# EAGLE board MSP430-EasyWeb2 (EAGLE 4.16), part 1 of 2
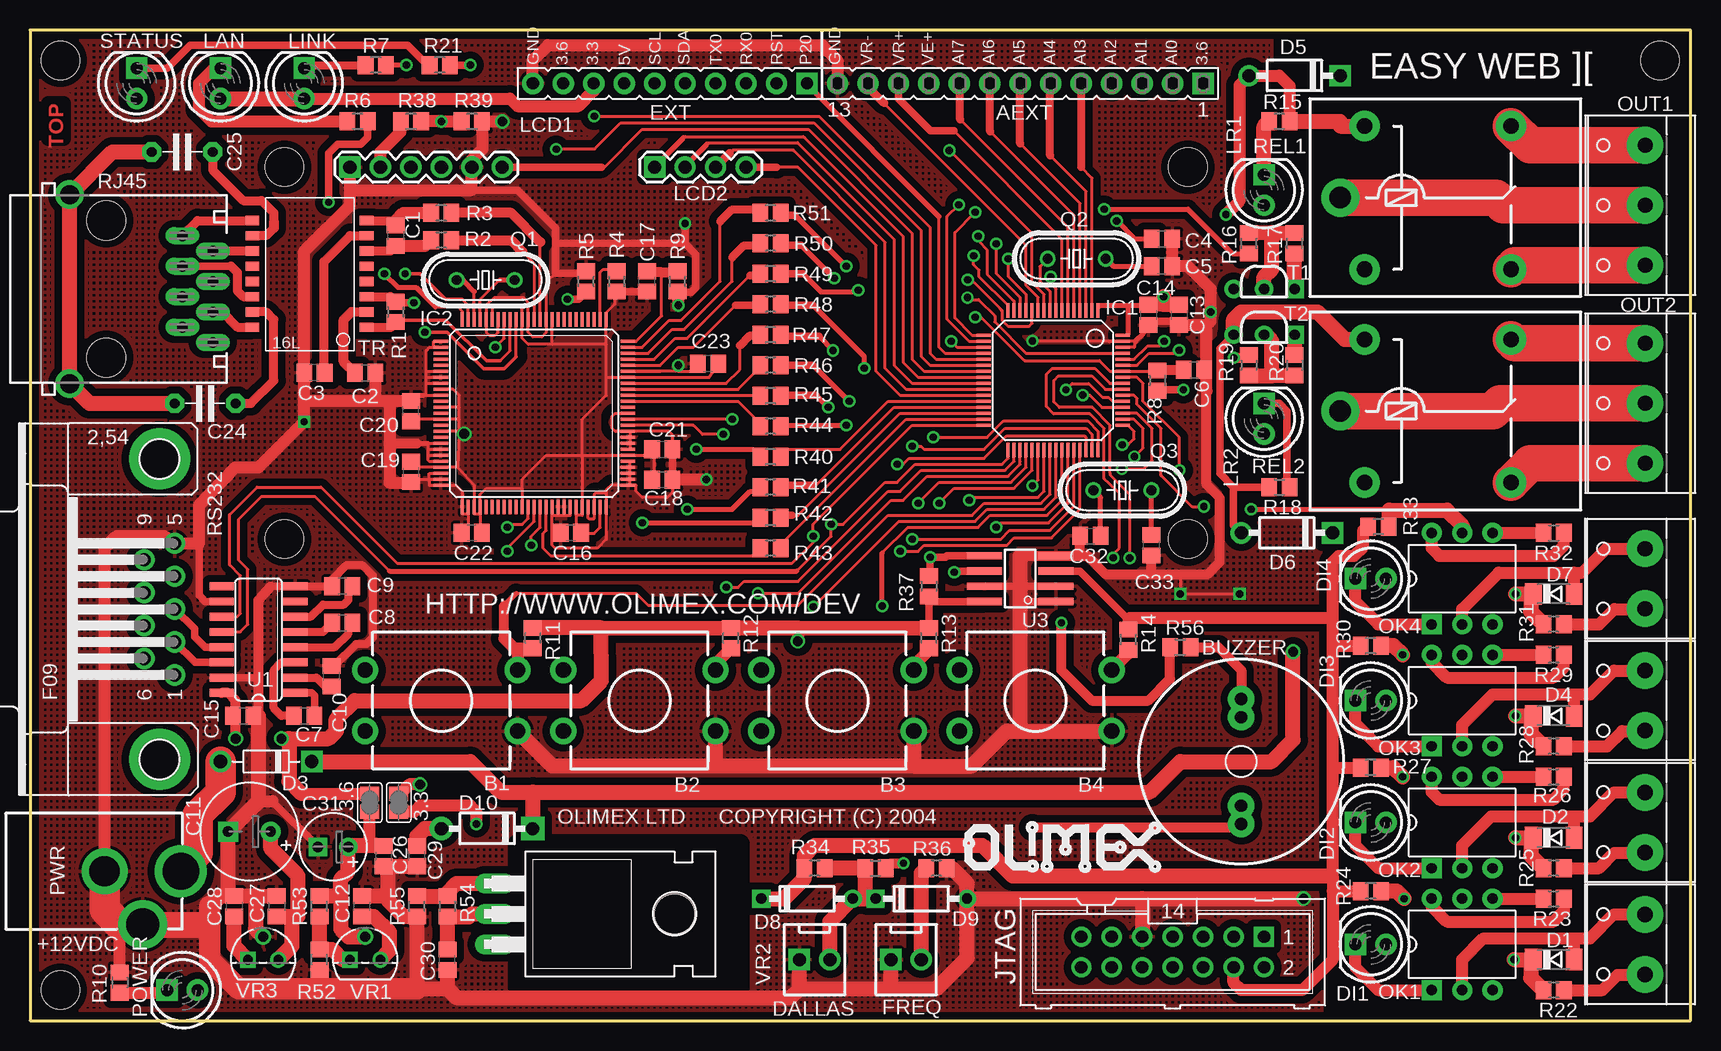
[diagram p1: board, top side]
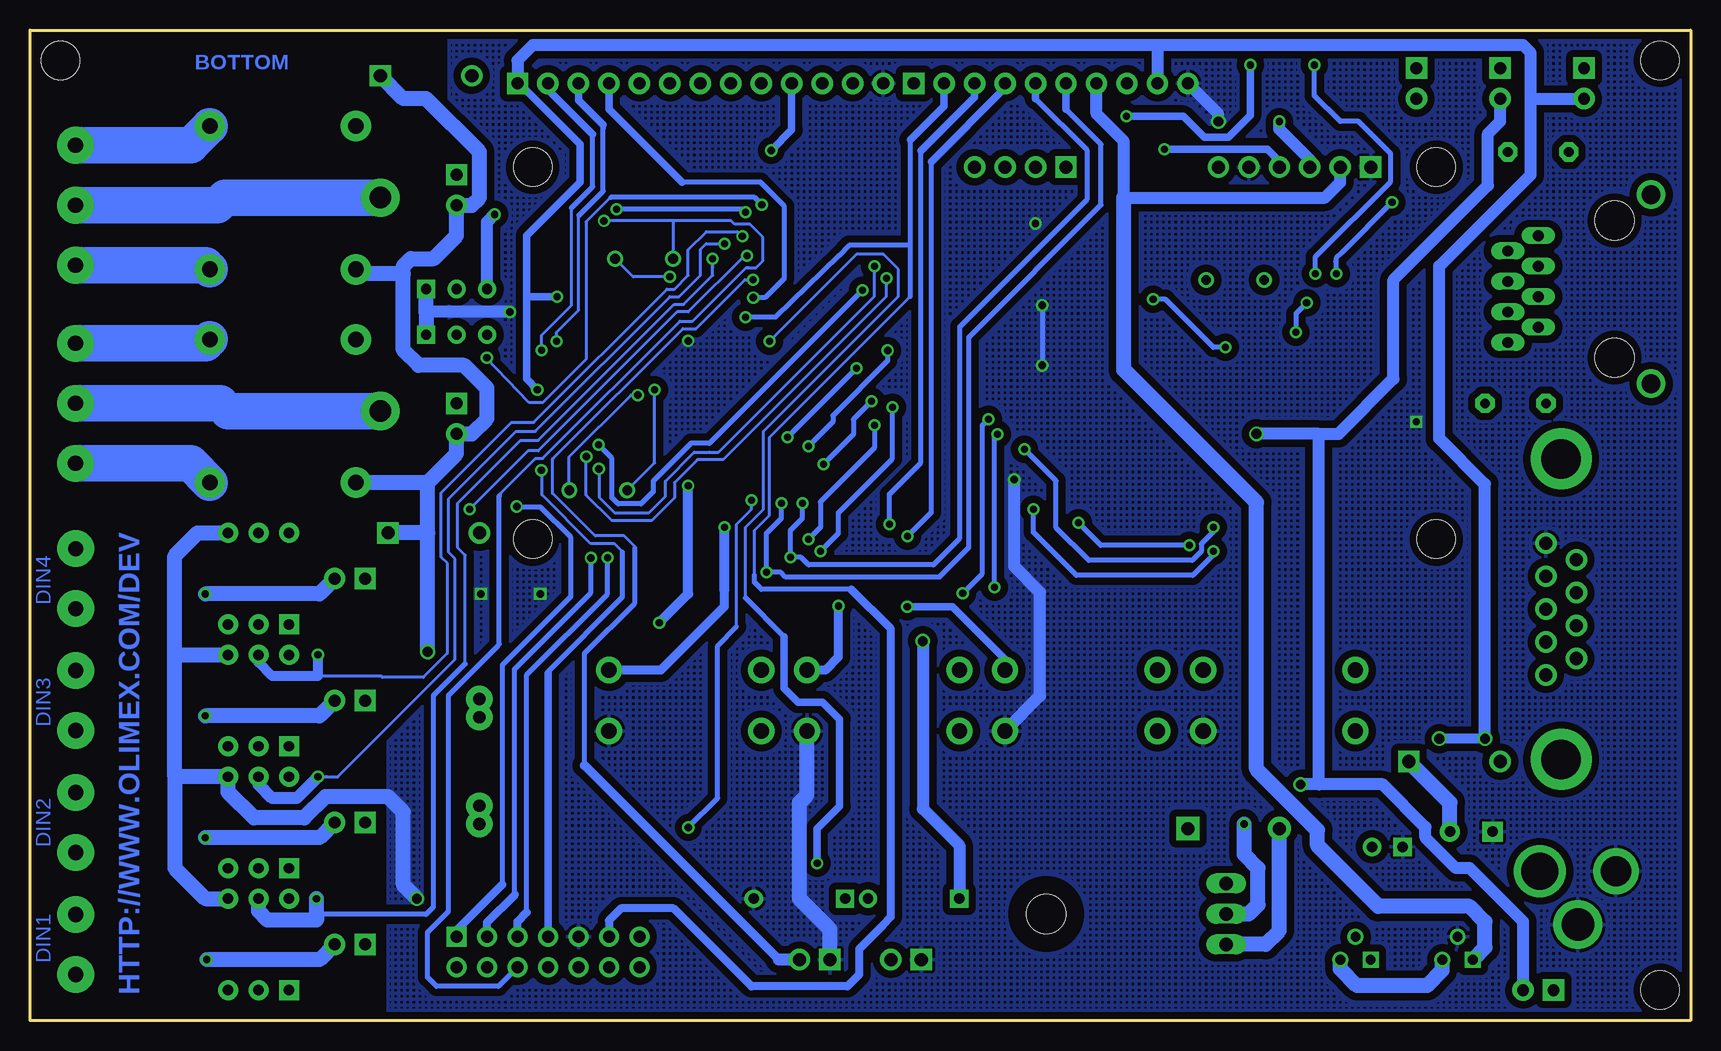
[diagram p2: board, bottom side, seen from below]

Size 138.43 x 82.55 mm. Coordinates in mm from the lower left corner, seen from the top.
Outline: 0,0 138.43,0 138.43,82.55 0,82.55 0,0
Copper layers (1*16): Top 0.035mm / dielectric 1.5mm / Bottom 0.035mm
Design rules "default": minimum track width 0.2489mm, minimum drill 24mil, track to track 9.5mil, track to pad 9.5mil, pad to pad 9.5mil, via to via 10mil, smd to smd 5mil, copper to edge 20mil, drill to drill 10mil, minimum pad ring 10mil, minimum via ring 8mil, stop-mask expansion 4mil, vias tented up to drill 25mil, thermal gap 10mil
Net classes: 0 default: width 0.241 mm, drill 0.241 mm, clearance 0.61 mm; 1 PWR: width 0.241 mm, drill 0.241 mm, clearance 0.61 mm
Holes 3.2 mm at 2.54,2.54 96.52,71.12 2.54,80.01 135.89,80.01 21.21,71.12 21.21,40.13 96.52,40.13
tRestrict: area 40.6,2.8 to 59.2,14.7

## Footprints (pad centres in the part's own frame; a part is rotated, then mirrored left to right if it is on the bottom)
SJ = smd 1.168 x 1.6: 1 -0.762,0; 2 0.762,0
FE13 = drill 1.016 pad 1.778 square: 1 -15.24,0 | drill 1.016 pad 1.778 round: 2 -12.7,0; 3 -10.16,0; 4 -7.62,0; 5 -5.08,0; 6 -2.54,0; 7 0,0; 8 2.54,0; 9 5.08,0; 10 7.62,0; 11 10.16,0; 12 12.7,0; 13 15.24,0
SW_TAKT12X12 = drill 1.27 pad 2.184 round: P$1 -2.54,-6.35; P$2 2.54,-6.35; P$3 2.54,6.35; P$4 -2.54,6.35
BUZ1 = drill 1.016 pad 2.184 round: + 5.207,0; - -5.207,0; P$1 -3.683,0; P$2 3.683,0
C0805 = smd 1.3 x 1.5: 1 -0.85,0; 2 0.85,0
E3,5-8 = drill 0.864 pad 1.676 round: + -1.778,0 | drill 0.864 pad 1.676 square: - 1.778,0
C-5 = drill 0.813 pad 1.6 octagon: 1 -2.54,0; 2 2.54,0
E2,5-6 = drill 0.864 pad 1.524 round: + -1.27,0 | drill 0.864 pad 1.524 square: - 1.27,0
SOD80C = smd 1.4 x 1.8: A 1.7,0; C -1.7,0
D-7.5 = drill 1.092 pad 1.778 round: A 3.81,0 | drill 1.092 pad 1.778 square: C -3.81,0
DO41-10 = drill 1.092 pad 1.778 round: A 3.81,0 | drill 1.092 pad 1.778 square: K -3.81,0
DO35-10 = drill 0.864 pad 1.524 round: A 3.81,0 | drill 0.864 pad 1.524 square: K -3.81,0
1N4742 = drill 1.092 pad 1.93 round: A 3.81,0 | drill 1.092 pad 1.93 square: K -3.81,0
CON2.54MM-2-0 = drill 1.092 pad 1.778 square: 1 -1.27,0 | drill 1.092 pad 1.778 round: 2 1.27,0
LED-5.0MM = drill 0.991 pad 1.778 round: A -1.27,0 | drill 0.991 pad 1.778 square: K 1.27,0
W237-102 = drill 1.27 pad 3.048 round: 1 -2.5,-1.27; 2 2.5,-1.27
FE10 = drill 1.016 pad 1.778 square: 1 -11.43,0 | drill 1.016 pad 1.778 round: 2 -8.89,0; 3 -6.35,0; 4 -3.81,0; 5 -1.27,0; 6 1.27,0; 7 3.81,0; 8 6.35,0; 9 8.89,0; 10 11.43,0
S-PQFP-G = smd 0.25 x 1.2: 1 -3.75,-5.8; 2 -3.25,-5.8; 3 -2.75,-5.8; 4 -2.25,-5.8; 5 -1.75,-5.8; 6 -1.25,-5.8; 7 -0.75,-5.8; 8 -0.25,-5.8; 9 0.25,-5.8; 10 0.75,-5.8; 11 1.25,-5.8; 12 1.75,-5.8; 13 2.25,-5.8; 14 2.75,-5.8; 15 3.25,-5.8; 16 3.75,-5.8; 33 3.75,5.8; 34 3.25,5.8; 35 2.75,5.8; 36 2.25,5.8; 37 1.75,5.8; 38 1.25,5.8; 39 0.75,5.8; 40 0.25,5.8; 41 -0.25,5.8; 42 -0.75,5.8; 43 -1.25,5.8; 44 -1.75,5.8; 45 -2.25,5.8; 46 -2.75,5.8; 47 -3.25,5.8; 48 -3.75,5.8 | smd 1.2 x 0.25: 17 5.8,-3.75; 18 5.8,-3.25; 19 5.8,-2.75; 20 5.8,-2.25; 21 5.8,-1.75; 22 5.8,-1.25; 23 5.8,-0.75; 24 5.8,-0.25; 25 5.8,0.25; 26 5.8,0.75; 27 5.8,1.25; 28 5.8,1.75; 29 5.8,2.25; 30 5.8,2.75; 31 5.8,3.25; 32 5.8,3.75; 49 -5.8,3.75; 50 -5.8,3.25; 51 -5.8,2.75; 52 -5.8,2.25; 53 -5.8,1.75; 54 -5.8,1.25; 55 -5.8,0.75; 56 -5.8,0.25; 57 -5.8,-0.25; 58 -5.8,-0.75; 59 -5.8,-1.25; 60 -5.8,-1.75; 61 -5.8,-2.25; 62 -5.8,-2.75; 63 -5.8,-3.25; 64 -5.8,-3.75
100LTQFP = smd 0.25 x 1.2: 1 -6,-7.8; 2 -5.5,-7.8; 3 -5,-7.8; 4 -4.5,-7.8; 5 -4,-7.8; 6 -3.5,-7.8; 7 -3,-7.8; 8 -2.5,-7.8; 9 -2,-7.8; 10 -1.5,-7.8; 11 -1,-7.8; 12 -0.5,-7.8; 13 0,-7.8; 14 0.5,-7.8; 15 1,-7.8; 16 1.5,-7.8; 17 2,-7.8; 18 2.5,-7.8; 19 3,-7.8; 20 3.5,-7.8; 21 4,-7.8; 22 4.5,-7.8; 23 5,-7.8; 24 5.5,-7.8; 25 6,-7.8; 51 6,7.8; 52 5.5,7.8; 53 5,7.8; 54 4.5,7.8; 55 4,7.8; 56 3.5,7.8; 57 3,7.8; 58 2.5,7.8; 59 2,7.8; 60 1.5,7.8; 61 1,7.8; 62 0.5,7.8; 63 0,7.8; 64 -0.5,7.8; 65 -1,7.8; 66 -1.5,7.8; 67 -2,7.8; 68 -2.5,7.8; 69 -3,7.8; 70 -3.5,7.8; 71 -4,7.8; 72 -4.5,7.8; 73 -5,7.8; 74 -5.5,7.8; 75 -6,7.8 | smd 1.2 x 0.25: 26 7.8,-6; 27 7.8,-5.5; 28 7.8,-5; 29 7.8,-4.5; 30 7.8,-4; 31 7.8,-3.5; 32 7.8,-3; 33 7.8,-2.5; 34 7.8,-2; 35 7.8,-1.5; 36 7.8,-1; 37 7.8,-0.5; 38 7.8,0; 39 7.8,0.5; 40 7.8,1; 41 7.8,1.5; 42 7.8,2; 43 7.8,2.5; 44 7.8,3; 45 7.8,3.5; 46 7.8,4; 47 7.8,4.5; 48 7.8,5; 49 7.8,5.5; 50 7.8,6; 76 -7.8,6; 77 -7.8,5.5; 78 -7.8,5; 79 -7.8,4.5; 80 -7.8,4; 81 -7.8,3.5; 82 -7.8,3; 83 -7.8,2.5; 84 -7.8,2; 85 -7.8,1.5; 86 -7.8,1; 87 -7.8,0.5; 88 -7.8,0; 89 -7.8,-0.5; 90 -7.8,-1; 91 -7.8,-1.5; 92 -7.8,-2; 93 -7.8,-2.5; 94 -7.8,-3; 95 -7.8,-3.5; 96 -7.8,-4; 97 -7.8,-4.5; 98 -7.8,-5; 99 -7.8,-5.5; 100 -7.8,-6
ML14 = drill 1.016 pad 1.676 square: 1 -7.62,-1.27 | drill 1.016 pad 1.676 round: 2 -7.62,1.27; 3 -5.08,-1.27; 4 -5.08,1.27; 5 -2.54,-1.27; 6 -2.54,1.27; 7 0,-1.27; 8 0,1.27; 9 2.54,-1.27; 10 2.54,1.27; 11 5.08,-1.27; 12 5.08,1.27; 13 7.62,-1.27; 14 7.62,1.27
HEADER2.54-6-0 = drill 1.092 pad 1.778 square: 1 -6.35,0 | drill 1.092 pad 1.778 round: 2 -3.81,0; 3 -1.27,0; 4 1.27,0; 5 3.81,0; 6 6.35,0
HEADER2.54-4-0 = drill 1.092 pad 1.778 square: 1 -3.81,0 | drill 1.092 pad 1.778 round: 2 -1.27,0; 3 1.27,0; 4 3.81,0
DIL06 = drill 0.864 pad 1.676 square: 1 -2.54,-3.81 | drill 0.864 pad 1.676 round: 2 0,-3.81; 3 2.54,-3.81; 4 2.54,3.81; 5 0,3.81; 6 -2.54,3.81
W237-103 = drill 1.27 pad 3.048 round: 1 -5,-1.29; 2 0,-1.29; 3 5,-1.29
PWR-JACK2 = drill 3.048 pad 4.318 round: + -0.127,4.826 | drill 2.54 pad 3.81 round: - -6.477,4.826 | drill 2.718 pad 4.064 round: -- -3.302,0.381
HC49/S = drill 0.813 round: 1 -2.413,0; 2 2.413,0
R0805 = smd 1.3 x 1.5: 1 -0.85,0; 2 0.85,0
H200-FAT = drill 1.295 pad 2.54 round: 1 -7.493,-5.969; 2 -7.493,5.969; O 4.699,5.969; S 4.699,-5.969 | drill 1.803 pad 3.175 round: P -9.525,0
555153-1 = drill 0.889 long: 1 -4.445,6.35; 2 -3.175,8.89; 3 -1.905,6.35; 4 -0.635,8.89; 5 0.635,6.35; 6 1.905,8.89; 7 3.175,6.35; 8 4.445,8.89 | drill 1.575 pad 2.184 round: G1 -7.874,-3.048; G2 7.874,-3.048 | hole 3.251: -5.715,0; 5.715,0
F09HP = drill 1.092 pad 1.778 round: 1 -5.486,-1.27; 2 -2.743,-1.27; 3 0,-1.27; 4 2.743,-1.27; 5 5.486,-1.27; 6 -4.115,1.27; 7 -1.372,1.27; 8 1.372,1.27; 9 4.115,1.27 | drill 3.302 pad 5.08 round: G1 -12.522,0; G2 12.522,0
TO92-M = drill 0.864 pad 1.524 square: 1 -2.54,0 | drill 0.864 pad 1.524 round: 2 0,0; 3 2.54,0
SO-16L = smd 0.762 x 1.143: 1 -3.81,-4.648; 2 -2.54,-4.648; 3 -1.27,-4.648; 4 0,-4.648; 5 1.27,-4.648; 6 2.54,-4.648; 7 3.81,-4.648; 8 5.08,-4.648; 9 5.08,4.877; 10 3.81,4.877; 11 2.54,4.877; 12 1.27,4.877; 13 0,4.877; 14 -1.27,4.877; 15 -2.54,4.877; 16 -3.81,4.877
SO16-150MILS = smd 0.66 x 2.032: 1 -4.445,-3.073; 2 -3.175,-3.073; 3 -1.905,-3.073; 4 -0.635,-3.073; 5 0.635,-3.073; 6 1.905,-3.073; 7 3.175,-3.073; 8 4.445,-3.073; 9 4.445,3.073; 10 3.175,3.073; 11 1.905,3.073; 12 0.635,3.073; 13 -0.635,3.073; 14 -1.905,3.073; 15 -3.175,3.073; 16 -4.445,3.073
SO-08MN = smd 0.61 x 2.921: 1 -1.905,-2.981; 2 -0.635,-2.981; 3 0.635,-2.981; 4 1.905,-2.981; 5 1.905,2.981; 6 0.635,2.981; 7 -0.635,2.981; 8 -1.905,2.981
TO92 = drill 0.813 square: 1 -1.27,0 | drill 0.813 round: 2 0,1.905; 3 1.27,0
TO220H = drill 1.118 long: 1 -2.54,-10.16; 2 0,-10.16; 3 2.54,-10.16 | hole 3.302: 0,4.826

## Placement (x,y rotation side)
3.3  SJ  [SJ]  30.73,18.16 90 top
3.6  SJ  [SJ]  28.32,18.16 90 top
AEXT  [FE13]  82.55,78.11 180 top
B1  [SW_TAKT12X12]  34.29,26.67 90 top
B2  [SW_TAKT12X12]  50.8,26.67 90 top
B3  [SW_TAKT12X12]  67.31,26.67 90 top
B4  [SW_TAKT12X12]  83.82,26.67 90 top
BUZZER  [BUZ1]  100.97,21.59 90 top
C1  560p  [C0805]  30.48,65.41 270 top
C2  100n  [C0805]  27.94,53.98 0 top
C3  100n  [C0805]  23.71,53.98 180 top
C4  15pF  [C0805]  94.36,65.15 0 top
C5  15pF  [C0805]  94.36,62.86 180 top
C6  100n  [C0805]  97.03,54.23 0 top
C7  100n  [C0805]  22.86,25.4 0 top
C8  100n  [C0805]  26.04,33.15 0 top
C9  100n  [C0805]  26.04,36.2 180 top
C10  100n  [C0805]  25.15,28.7 90 top
C11  220uF/25VDC  [E3,5-8]  18.29,15.75 180 top
C12  100n  [C0805]  27.69,9.52 90 top
C13  100n  [C0805]  95.76,58.8 270 top
C14  100n  [C0805]  93.22,58.8 270 top
C15  100n  [C0805]  17.78,25.4 0 top
C16  100n  [C0805]  45.09,40.64 180 top
C17  100n  [C0805]  51.44,61.59 90 top
C18  100n  [C0805]  52.7,45.09 0 top
C19  100n  [C0805]  31.75,45.72 270 top
C20  100n  [C0805]  31.75,50.8 90 top
C21  100n  [C0805]  52.7,47.62 0 top
C22  100n  [C0805]  36.83,40.64 180 top
C23  100n  [C0805]  56.52,54.74 180 top
C24  4n7  [C-5]  14.6,51.43 0 top
C25  4n7  [C-5]  12.69,72.39 0 top
C26  100n  [C0805]  29.46,13.72 270 top
C27  100n  [C0805]  20.57,9.52 270 top
C28  100n  [C0805]  17.02,9.52 270 top
C29  100n  [C0805]  32.26,13.72 90 top
C30  100n  [C0805]  34.8,5.08 90 top
C31  100uF  [E2,5-6]  25.27,14.48 180 top
C32  NA  [C0805]  88.39,40.39 0 top
C33  NA  [C0805]  93.47,39.62 90 top
D1  1N4148  [SOD80C]  127,5.08 0 top
D2  1N4148  [SOD80C]  127,15.24 0 top
D3  1N4004  [D-7.5]  19.68,21.59 180 top
D4  1N4148  [SOD80C]  127,25.4 0 top
D5  1N4004  [DO41-10]  105.41,78.74 180 top
D6  1N4004  [DO41-10]  104.78,40.64 180 top
D7  1N4148  [SOD80C]  127,35.56 0 top
D8  1N4148  [DO35-10]  64.77,10.16 0 top
D9  1N4148  [DO35-10]  74.3,10.16 0 top
D10  1N4730  [1N4742]  38.1,16 180 top
DALLAS  [CON2.54MM-2-0]  65.41,5.08 0 top
DI1  [LED-5.0MM]  111.76,6.35 180 top
DI2  [LED-5.0MM]  111.76,16.51 180 top
DI3  [LED-5.0MM]  111.76,26.67 180 top
DI4  [LED-5.0MM]  111.76,36.83 180 top
DIN1  [W237-102]  133.35,6.35 90 top
DIN2  [W237-102]  133.35,16.51 90 top
DIN3  [W237-102]  133.35,26.67 90 top
DIN4  [W237-102]  133.35,36.83 90 top
EXT  [FE10]  53.34,78.11 180 top
FREQ  [CON2.54MM-2-0]  73.03,5.08 0 top
IC1  MSP430F149  [S-PQFP-G]  85.29,53.36 180 top
IC2  CS8900A  [100LTQFP]  42.04,50.61 270 top
JTAG  [ML14]  95.25,5.71 180 top
LAN  [LED-5.0MM]  15.88,78.11 90 top
LCD1  [HEADER2.54-6-0]  33.02,71.12 0 top
LCD2  [HEADER2.54-4-0]  55.88,71.12 0 top
LINK  [LED-5.0MM]  22.86,78.11 90 top
LR1  [LED-5.0MM]  102.87,69.22 90 top
LR2  [LED-5.0MM]  102.87,50.16 90 top
OK1  4N37  [DIL06]  119.38,6.35 0 top
OK2  4N37  [DIL06]  119.38,16.51 0 top
OK3  4N37  [DIL06]  119.38,26.67 0 top
OK4  4N37  [DIL06]  119.38,36.83 0 top
OUT1  [W237-103]  133.35,67.94 90 top
OUT2  [W237-103]  133.35,51.44 90 top
POWER  [LED-5.0MM]  12.7,2.54 180 top
PWR  [PWR-JACK2]  12.7,7.62 0 top
Q1  20MHz  [HC49/S]  37.97,61.72 0 top
Q2  8MHz  [HC49/S]  87.25,63.49 0 top
Q3  NA  [HC49/S]  91.06,44.2 180 top
R1  100  [R0805]  30.48,59.05 270 top
R2  8.2/1%  [R0805]  34.29,65.02 180 top
R3  8.2/1%  [R0805]  34.29,67.31 180 top
R4  4.7K  [R0805]  48.89,61.59 270 top
R5  4.99K,1%  [R0805]  46.35,61.59 90 top
R6  560  [R0805]  27.3,74.93 180 top
R7  560  [R0805]  28.83,79.63 180 top
R8  100k  [R0805]  93.98,53.34 270 top
R9  100K  [R0805]  53.98,61.59 90 top
R10  560  [R0805]  7.49,3.17 270 top
R11  10K  [R0805]  41.91,31.88 90 top
R12  10K  [R0805]  58.42,31.88 90 top
R13  10K  [R0805]  74.93,31.88 90 top
R14  10K  [R0805]  91.57,31.75 90 top
R15  1.5K  [R0805]  104.14,74.93 180 top
R16  2K  [R0805]  101.6,64.77 90 top
R17  10K  [R0805]  105.41,64.77 90 top
R18  1.5K  [R0805]  104.14,44.45 0 top
R19  2K  [R0805]  101.6,54.61 270 top
R20  10K  [R0805]  105.41,54.61 270 top
R21  330  [R0805]  34.16,79.63 180 top
R22  330  [R0805]  127,2.54 180 top
R23  270K  [R0805]  127,10.16 0 top
R24  10K  [R0805]  111.76,10.79 180 top
R25  330  [R0805]  127,12.7 180 top
R26  270K  [R0805]  127,20.32 0 top
R27  10K  [R0805]  111.76,21.08 180 top
R28  330  [R0805]  127,22.86 180 top
R29  270K  [R0805]  127,30.48 0 top
R30  10K  [R0805]  111.76,31.24 180 top
R31  330  [R0805]  127,33.02 180 top
R32  270K  [R0805]  127,40.64 0 top
R33  10K  [R0805]  112.4,41.15 180 top
R34  1K  [R0805]  65.41,12.7 180 top
R35  22  [R0805]  70.48,12.7 0 top
R36  100K  [R0805]  75.57,12.7 180 top
R37  2K  [R0805]  74.93,36.2 270 top
R38  10K  [R0805]  31.75,74.93 180 top
R39  1K  [R0805]  36.83,74.93 180 top
R40  100  [R0805]  61.73,46.99 180 top
R41  100  [R0805]  61.73,44.45 180 top
R42  100  [R0805]  61.73,41.91 180 top
R43  100  [R0805]  61.73,39.37 180 top
R44  100  [R0805]  61.73,49.53 180 top
R45  100  [R0805]  61.73,52.07 180 top
R46  100  [R0805]  61.73,54.61 180 top
R47  100  [R0805]  61.73,57.15 180 top
R48  100  [R0805]  61.73,59.69 180 top
R49  100  [R0805]  61.73,62.23 180 top
R50  100  [R0805]  61.73,64.77 180 top
R51  100  [R0805]  61.73,67.31 180 top
R52  330/1%  [R0805]  24.13,5.08 90 top
R53  180/1%  [R0805]  24.13,9.52 90 top
R54  240/1%  [R0805]  34.8,9.52 270 top
R55  390/1%  [R0805]  32.26,9.52 90 top
R56  330  [R0805]  95.89,31.12 0 top
REL1  [H200-FAT]  118.75,68.58 0 top
REL2  [H200-FAT]  118.75,50.8 0 top
RJ45  [555153-1]  6.35,60.96 270 top
RS232  [F09HP]  10.8,34.29 90 top
STATUS  [LED-5.0MM]  8.89,78.11 90 top
T1  BC337-40  [TO92-M]  102.87,60.96 180 top
T2  BC337-40  [TO92-M]  102.87,57.15 180 top
TR  E2023  [SO-16L]  23.42,61.59 90 top
U1  MAX3232  [SO16-150MILS]  19.05,31.75 90 top
U3  24LC515  [SO-08MN]  82.55,36.83 90 top
U$1  [OLIMEX1]  77.76,12.34 0 top
VR1  LM317L  [TO92]  27.94,5.08 0 top
VR2  317T  [TO220H]  48.89,8.89 270 top
VR3  78L05  [TO92]  19.43,5.08 0 top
